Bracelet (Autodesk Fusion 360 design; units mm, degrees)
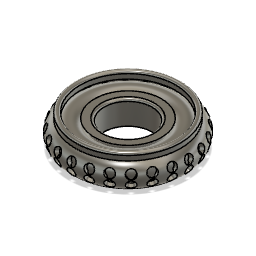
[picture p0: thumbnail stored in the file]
sketch "Sketch1" plane through (0, 0, 0) normal (0, 0, 1) x axis (1, 0, 0)
  line L1 (-200, -50) -> (-220, -50)
  line L2 (-200, 50) -> (-220, 50)
  line L3 (-200, 80) -> (-200, 50)
  line L4 (-220, 80) -> (-200, 80)
  line L5 (-220, 50) -> (-220, 80)
  line L6 (-100, 50) -> (-140, 50)
  line L7 (-100, -50) -> (-100, 50)
  line L8 (-140, -50) -> (-100, -50)
  arc A1 centre (-173.3333, 0) radius 56.6667 clockwise from (-200, -50) to (-200, 50)
  arc A2 centre (-193.3333, 0) radius 56.6667 clockwise from (-220, -50) to (-220, 50)
  circle C1 centre (-173.3333, 0) radius 51.652
  arc A3 centre (-176.9989, 0) radius 62.2006 clockwise from (-140, 50) to (-140, -50)
  point P16 (-100, -50)
  concentric A1 C1
  horizontal L1
  horizontal L2
  vertical L3
  horizontal L4
  vertical L5
  horizontal L6
  perpendicular L6 L7
  coincident L7 P16
  perpendicular L7 L8
revolve "Revolve1" sketch "Sketch1" AlongAngle 360
sketch "Sketch2" plane through (0, 0, 0) normal (1, 0, 0) x axis (0, 0, -1)
sketch "Sketch3" plane through (0, 0, 0) normal (1, 0, 0) x axis (0, 0, -1)
sketch "Sketch4" plane through (0, 0, 0) normal (0, 0, 1) x axis (1, 0, 0)
  circle C1 centre (-75, 250) radius 35.3553
extrude "Extrude1" new body sketch "Sketch4" along normal blind 15
hole "Hole1" HoleDepth 25 HoleDiameter 35 TipAngle 180
circular_pattern "C-Pattern1" countU 24 TotalAngle 360
mirror "Mirror1" mirrorStitchTolerance 0.1
mirror "Mirror2" mirrorStitchTolerance 0.1
fillet "Fillet1" radius 10 10
fillet "Fillet2" radius 10 10
remove_body "RemoveBody1"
